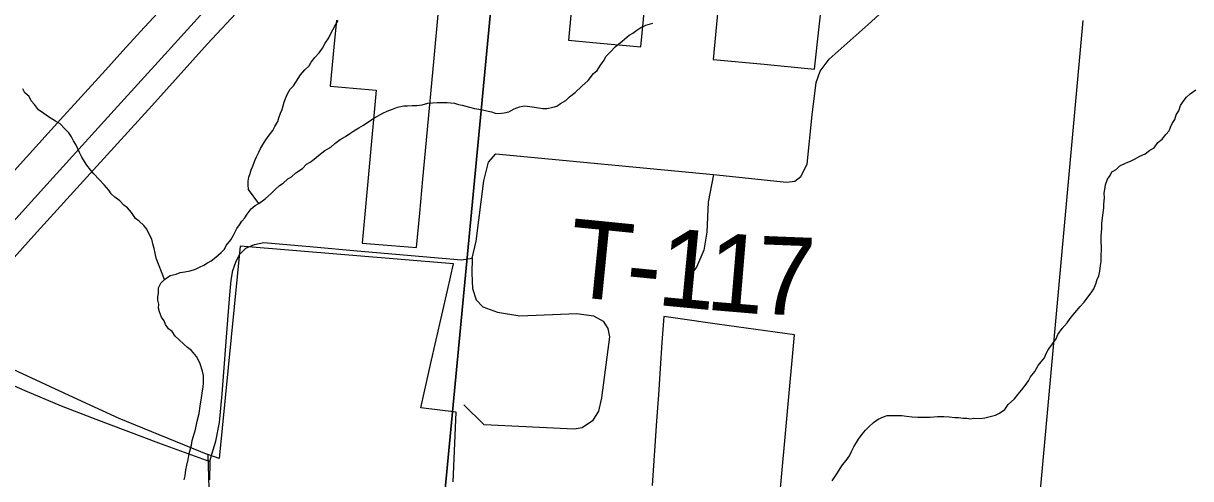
# Model space of a CAD drawing. Extents: x -7.3 to 34, y 0 to 22.
# Drawn here: x 7.321 to 8.172, y 17.405 to 17.736 of the extents above; entities that cross this region are included whole.
import ezdxf

# ---------------------------------------------------------------- set-up
doc = ezdxf.new("R2010")
doc.units = 0
for name, color, linetype in [('GM_X_City_Street', 7, 'Continuous'), ('GM_X_Corporation', 7, 'Continuous'), ('GM_X_County_Road', 7, 'Continuous'), ('GM_X_Interstate_Route', 7, 'Continuous'), ('GM_X_Minor_River', 7, 'Continuous'), ('GM_X_Township_Road', 7, 'Continuous'), ('GM_X_Township_Road_Text', 7, 'Continuous')]:
    doc.layers.add(name, color=color, linetype=linetype)

msp = doc.modelspace()

# ---------------------------------------------------------------- linework, layer by layer
at = {"layer": 'GM_X_City_Street'}
msp.add_lwpolyline([(7.93651, 17.73563), (8.01802, 17.80971), (8.02246, 17.81381), (8.02868, 17.82053), (8.0344, 17.82683), (8.03877, 17.8336), (8.04091, 17.83966), (8.04794, 17.90717), (8.05805, 18.01178), (8.06114, 18.04249), (8.06275, 18.06253), (8.06395, 18.08702), (8.06615, 18.11765)], dxfattribs=at)
at = {"layer": 'GM_X_Corporation'}
for points in [[(7.67368, 17.87494), (7.57814, 16.87092), (6.52813, 16.95829), (6.6194, 17.97528)], [(8.68934, 17.73712), (8.59422, 16.71681), (7.57814, 16.87092), (7.67368, 17.87494)]]:
    msp.add_lwpolyline(points, close=True, dxfattribs=at)
for points in [[(7.72381, 17.784), (7.71817, 17.72416), (7.73578, 17.7225), (7.77091, 17.71919), (7.77671, 17.77929)], [(7.82978, 17.77459), (7.82352, 17.71015), (7.86079, 17.70653), (7.89496, 17.70321), (7.89746, 17.70297), (7.90417, 17.76492)], [(7.41841, 17.74386), (7.40599, 17.73044), (7.39321, 17.71637), (7.38043, 17.70229), (7.35522, 17.67454), (7.34987, 17.66864), (7.31377, 17.62886)], [(7.54883, 17.73863), (7.54702, 17.719), (7.54441, 17.69059), (7.57795, 17.68776), (7.57255, 17.62909), (7.56768, 17.57628), (7.58295, 17.57499), (7.60731, 17.57294), (7.60962, 17.59802), (7.61191, 17.62291), (7.61452, 17.6512), (7.62003, 17.71103), (7.62321, 17.74558)], [(8.09314, 17.73848), (8.05978, 17.37231)], [(7.63396, 17.40219), (7.63616, 17.45317), (7.61042, 17.45625), (7.61759, 17.4877), (7.62987, 17.54162), (7.63432, 17.56115), (7.47866, 17.57409), (7.4633, 17.41931), (7.46008, 17.42061), (7.4551, 17.42223), (7.45725, 17.34864)], [(7.8722, 17.3924), (7.88292, 17.50933), (7.82647, 17.51724), (7.79775, 17.52126), (7.78753, 17.52269), (7.78623, 17.50372), (7.78493, 17.48475), (7.78363, 17.46579), (7.78233, 17.44682), (7.77909, 17.39957)], [(7.30985, 17.48592), (7.35694, 17.46404), (7.39031, 17.44862), (7.4551, 17.42223), (7.45725, 17.34864)]]:
    msp.add_lwpolyline(points, dxfattribs=at)
at = {"layer": 'GM_X_County_Road'}
for points in [[(7.27133, 17.4907), (7.32159, 17.46885), (7.34827, 17.45772), (7.37336, 17.44794), (7.41922, 17.43081), (7.45662, 17.41714)], [(7.45662, 17.41714), (7.45639, 17.40375)]]:
    msp.add_lwpolyline(points, dxfattribs=at)
at = {"layer": 'GM_X_Interstate_Route'}
for points in [[(7.29247, 17.56917), (7.33767, 17.61907), (7.38676, 17.67308), (7.42372, 17.7137), (7.46869, 17.76348), (7.50783, 17.80765), (7.54433, 17.85011), (7.59388, 17.90858), (7.63393, 17.95562), (7.67055, 17.99876), (7.70491, 18.03855), (7.75157, 18.09065), (7.78603, 18.12903), (7.79225, 18.13582), (7.80713, 18.15204), (7.84266, 18.19129), (7.88221, 18.23423), (7.92254, 18.27906), (7.94779, 18.30676)], [(7.24965, 17.49492), (7.25306, 17.49864), (7.28852, 17.53775), (7.3283, 17.58187), (7.37171, 17.62954), (7.41433, 17.67618), (7.45489, 17.7214), (7.49609, 17.76592), (7.5406, 17.81272), (7.58188, 17.8551), (7.60137, 17.87502)]]:
    msp.add_lwpolyline(points, dxfattribs=at)
at = {"layer": 'GM_X_Minor_River'}
for points in [[(7.49222, 17.60519), (7.48485, 17.61523), (7.48454, 17.61866), (7.4846, 17.62132), (7.48504, 17.62435), (7.48586, 17.627), (7.48668, 17.62964), (7.48787, 17.63228), (7.48908, 17.63567), (7.49068, 17.63906), (7.49227, 17.64245), (7.49346, 17.64508), (7.49504, 17.64771), (7.49739, 17.65146), (7.49974, 17.65483), (7.50247, 17.65819), (7.50405, 17.6612), (7.50603, 17.66496), (7.50684, 17.6676), (7.50806, 17.671), (7.50925, 17.67364), (7.51007, 17.67628), (7.51088, 17.67892), (7.5117, 17.68157), (7.51329, 17.68495), (7.51526, 17.68833), (7.51759, 17.69095), (7.51917, 17.69357), (7.52269, 17.69882), (7.52581, 17.70255), (7.52891, 17.70553), (7.53048, 17.70816), (7.53321, 17.71152), (7.53632, 17.71487), (7.53866, 17.71824), (7.54064, 17.722), (7.54338, 17.72575), (7.54458, 17.72838), (7.54617, 17.73177), (7.54774, 17.7344), (7.55011, 17.73853)], [(7.50729, 17.61816), (7.50998, 17.62001), (7.51346, 17.62297), (7.51615, 17.62444), (7.51925, 17.62741), (7.52425, 17.63072), (7.52697, 17.63371), (7.52966, 17.63517), (7.53274, 17.63738), (7.53583, 17.63998), (7.54046, 17.64368), (7.54469, 17.64625), (7.54778, 17.64884), (7.55164, 17.6518), (7.55548, 17.654), (7.55856, 17.65621), (7.56164, 17.65805), (7.5651, 17.66025), (7.56855, 17.66208), (7.57317, 17.6654), (7.57664, 17.66761), (7.58278, 17.67089), (7.58584, 17.67235), (7.58967, 17.67379), (7.59349, 17.67523), (7.59806, 17.67627), (7.60072, 17.67621), (7.60414, 17.67652), (7.60755, 17.67644), (7.61136, 17.67712), (7.61555, 17.67817), (7.61897, 17.67847), (7.62239, 17.67878), (7.62618, 17.6787), (7.6296, 17.67862), (7.63225, 17.67856), (7.6349, 17.67813), (7.63791, 17.6773), (7.64056, 17.67686), (7.64583, 17.67523), (7.64961, 17.67438), (7.65452, 17.67352), (7.65942, 17.67227), (7.66207, 17.67183), (7.66471, 17.67101), (7.66735, 17.67058), (7.67116, 17.67125), (7.67459, 17.67194), (7.67843, 17.67414), (7.68225, 17.67558), (7.68606, 17.67625), (7.68984, 17.67579), (7.69325, 17.67534), (7.69627, 17.67489), (7.69929, 17.67444), (7.70233, 17.67438), (7.7069, 17.67542), (7.70957, 17.67612), (7.71227, 17.67796), (7.71611, 17.68016), (7.71882, 17.68277), (7.72306, 17.68609), (7.72771, 17.69056), (7.73235, 17.69464), (7.73626, 17.69988), (7.73896, 17.7021), (7.74132, 17.70585), (7.74406, 17.70959), (7.74525, 17.71223), (7.74874, 17.71558), (7.75223, 17.7193), (7.75725, 17.72338), (7.76228, 17.72783), (7.76496, 17.72929), (7.76805, 17.73151), (7.77074, 17.73335), (7.77458, 17.73517), (7.77953, 17.73658)], [(7.4235, 17.54965), (7.41739, 17.56537), (7.41671, 17.56881), (7.41602, 17.57225), (7.41496, 17.57569), (7.41427, 17.57913), (7.41282, 17.58182), (7.41064, 17.58643), (7.40842, 17.58914), (7.40508, 17.59226), (7.40247, 17.59421), (7.39952, 17.59846), (7.39656, 17.60195), (7.39395, 17.6039), (7.39098, 17.60701), (7.38725, 17.60975), (7.38465, 17.61209), (7.38281, 17.61479), (7.37948, 17.61867), (7.37577, 17.62255), (7.37207, 17.62681), (7.36947, 17.62953), (7.3669, 17.63301), (7.36506, 17.63571), (7.36323, 17.63879), (7.36141, 17.64225), (7.35888, 17.64801), (7.35704, 17.65071), (7.35559, 17.65379), (7.35375, 17.65649), (7.35078, 17.65959), (7.34744, 17.66309), (7.34407, 17.66506), (7.33883, 17.66822), (7.33547, 17.67057), (7.33173, 17.67332), (7.32878, 17.67718), (7.32619, 17.6799), (7.32474, 17.68298), (7.32176, 17.6857), (7.32031, 17.68877)], [(8.16435, 17.6765), (8.16631, 17.6795), (8.16865, 17.68249), (8.17136, 17.68509), (8.1756, 17.68805)], [(7.92607, 17.4277), (7.92961, 17.43332), (7.93234, 17.43706), (7.93468, 17.44005), (7.93739, 17.44266), (7.94049, 17.44563), (7.94396, 17.44784), (7.94779, 17.44965), (7.95046, 17.45073), (7.9535, 17.45067), (7.95729, 17.45059), (7.96108, 17.45051), (7.96448, 17.45005), (7.96865, 17.44958), (7.97282, 17.44949), (7.97775, 17.44938), (7.98191, 17.44929), (7.98458, 17.44961), (7.98724, 17.44994), (7.99179, 17.44984), (7.99558, 17.44975), (7.99974, 17.44928), (8.0024, 17.44923), (8.0058, 17.44877), (8.00845, 17.44872), (8.0111, 17.44828), (8.01376, 17.4486), (8.01831, 17.4485), (8.02173, 17.44881), (8.02554, 17.44986), (8.02936, 17.45092), (8.03243, 17.45238), (8.03628, 17.45495), (8.03863, 17.4587), (8.04327, 17.46278), (8.046, 17.46615), (8.04834, 17.46914), (8.05107, 17.4725), (8.05342, 17.47587), (8.055, 17.47888), (8.05812, 17.48261), (8.06049, 17.48712), (8.06282, 17.48973), (8.06516, 17.49272), (8.06637, 17.49574), (8.06794, 17.49837), (8.07107, 17.50286), (8.07381, 17.5066), (8.07501, 17.50962), (8.07814, 17.51411), (8.08165, 17.51822), (8.08399, 17.52121), (8.08594, 17.52383), (8.08867, 17.52719), (8.091, 17.5298), (8.09411, 17.53316), (8.09606, 17.53578), (8.09919, 17.53989), (8.10115, 17.54289), (8.10275, 17.54666), (8.10357, 17.54968), (8.10476, 17.55232), (8.1056, 17.55572), (8.10607, 17.55989), (8.10651, 17.56293), (8.10662, 17.56787), (8.10668, 17.57091), (8.10675, 17.57395), (8.10643, 17.57662), (8.10653, 17.58118), (8.10704, 17.58725), (8.10711, 17.59067), (8.10804, 17.59825), (8.1085, 17.60205), (8.10856, 17.60471), (8.10903, 17.60926), (8.10873, 17.61269), (8.10917, 17.61534), (8.10962, 17.61875), (8.11123, 17.6229), (8.11318, 17.62552), (8.11438, 17.62815), (8.11745, 17.62999), (8.12016, 17.63259), (8.12476, 17.63477), (8.12782, 17.63585), (8.13088, 17.6373), (8.13472, 17.6395), (8.13856, 17.64132), (8.14203, 17.64391), (8.1451, 17.64574), (8.14784, 17.64948), (8.15093, 17.65208), (8.15365, 17.65544), (8.15599, 17.65805), (8.15718, 17.66069), (8.15838, 17.66332), (8.16034, 17.66632), (8.16117, 17.66973), (8.16313, 17.67273), (8.16435, 17.6765)], [(7.43778, 17.40373), (7.4386, 17.40675), (7.43907, 17.41092), (7.4399, 17.41433), (7.44075, 17.41849), (7.44161, 17.42303), (7.44326, 17.42908), (7.44371, 17.43249), (7.44454, 17.43552), (7.44616, 17.44042), (7.44743, 17.44648), (7.44869, 17.45215), (7.44957, 17.45746), (7.45046, 17.46352), (7.45091, 17.46693), (7.45176, 17.47148), (7.45183, 17.47452), (7.45189, 17.47717), (7.45195, 17.47984), (7.45125, 17.48289), (7.44947, 17.48825), (7.4484, 17.49094), (7.44693, 17.49363), (7.44324, 17.49789), (7.44025, 17.50024), (7.43765, 17.50258), (7.4343, 17.50569), (7.43133, 17.50842), (7.42913, 17.51189), (7.42651, 17.51385), (7.4243, 17.51694), (7.42322, 17.51962), (7.42139, 17.52232), (7.41995, 17.52616), (7.41925, 17.52883), (7.41932, 17.53187), (7.41862, 17.53455), (7.41868, 17.53721), (7.41911, 17.53986), (7.4192, 17.54366), (7.42079, 17.54705), (7.4235, 17.54965), (7.42773, 17.5526), (7.43193, 17.55365), (7.43499, 17.55472), (7.43841, 17.55541), (7.44222, 17.55609), (7.44604, 17.55714), (7.4491, 17.5586), (7.45217, 17.56005), (7.45486, 17.56189), (7.45755, 17.56336), (7.46102, 17.56594), (7.46489, 17.56928), (7.46722, 17.57189), (7.46842, 17.57453), (7.47192, 17.57863), (7.47389, 17.58201), (7.47627, 17.5869), (7.47822, 17.58952), (7.4798, 17.59215), (7.48213, 17.59476), (7.4837, 17.59739), (7.48682, 17.60112), (7.48953, 17.60372), (7.49222, 17.60519), (7.49684, 17.60851), (7.50148, 17.61259), (7.50419, 17.61519), (7.50729, 17.61816)], [(7.91036, 17.40295), (7.91232, 17.40595), (7.91428, 17.40894), (7.91624, 17.41194), (7.91782, 17.41457), (7.92055, 17.41793), (7.9229, 17.4213), (7.92448, 17.42431), (7.92607, 17.4277)]]:
    msp.add_lwpolyline(points, dxfattribs=at)
at = {"layer": 'GM_X_Township_Road'}
for points in [[(7.45662, 17.41714), (7.45809, 17.42254), (7.46087, 17.43199), (7.46355, 17.44561), (7.46564, 17.4663), (7.46972, 17.52039), (7.47121, 17.53859), (7.4722, 17.54923), (7.47335, 17.55639), (7.47573, 17.56315), (7.47852, 17.56822), (7.48289, 17.5726), (7.48906, 17.57528), (7.49597, 17.57657), (7.53224, 17.57362), (7.56399, 17.57061), (7.63996, 17.56404), (7.64791, 17.56523), (7.65079, 17.57767), (7.65636, 17.62172), (7.65974, 17.63524), (7.66511, 17.64121), (7.82384, 17.62616), (7.8771, 17.62064), (7.88316, 17.62135), (7.88743, 17.62473), (7.89224, 17.63381), (7.89581, 17.6698), (7.89866, 17.69332), (7.90169, 17.7016), (7.90828, 17.71024), (7.93651, 17.73563)], [(7.82384, 17.62616), (7.81992, 17.60603), (7.81903, 17.5842), (7.81689, 17.5712), (7.81146, 17.55873), (7.80442, 17.54964)], [(7.64791, 17.56523), (7.64751, 17.5544), (7.64821, 17.54316), (7.65089, 17.53491), (7.65556, 17.52983), (7.6663, 17.52596), (7.68251, 17.52337), (7.72418, 17.52506), (7.73631, 17.52317), (7.74347, 17.5193), (7.74675, 17.51413), (7.74804, 17.50786), (7.74208, 17.46361), (7.73989, 17.45367), (7.73571, 17.44671), (7.72818, 17.44167), (7.72219, 17.44064), (7.65653, 17.44392), (7.64168, 17.45828)]]:
    msp.add_lwpolyline(points, dxfattribs=at)

# ---------------------------------------------------------------- texts
at = {"layer": 'GM_X_Township_Road_Text'}
for s, rotation, p in [('T', 354.33376, (7.71592, 17.53777)), ('1', 354.53766, (7.78166, 17.53127)), ('1', 355.23351, (7.81724, 17.52787)), ('7', 357.79143, (7.85488, 17.5248)), ('-', 354.40238, (7.75829, 17.53357))]:
    msp.add_text(s, height=0.05682, rotation=rotation, dxfattribs=at).set_placement(p)

doc.saveas('drawing.dxf')
